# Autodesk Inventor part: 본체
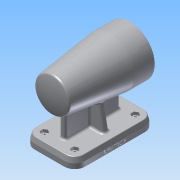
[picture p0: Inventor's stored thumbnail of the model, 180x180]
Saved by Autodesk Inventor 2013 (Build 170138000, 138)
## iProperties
Created: 2017-01
Part Number: 본체
Material: 알루미늄 6061
Document SubType Name: Modeling
Designer: Administrator
Density: 2.71 g/cm^3
Mass: 795.659 g
Surface Area: 660.761 cm^2
Volume: 293.601 cm^3
Author: Administrator
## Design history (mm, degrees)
sketch "스케치3"
  geometry: L1 (56, 35)-(-56, 35); L2 (-56, 35)-(-56, -35); L3 (-56, -35)-(56, -35); L4 (56, -35)-(56, 35); L5 (56, 35)-(-56, -35); L6 (-56, 35)-(56, -35); 3 further points
  constraints: 12 end point, 3 midpoint, 2 parallel, 1 coincident, 1 horizontal, 1 perpendicular
  dimensions: "d0" = 112 distance of L2.end L3.end; "d2" = 70 distance of L1.end L2.end
extrude "돌출1" new body sketch "스케치3" distance "d3" = 14; taper "d4" = 0 deg
sketch "스케치4"
  geometry: L1 (56, 0)-(-56, 0) reference; L2 (56, 74)-(-56, 74); L3 (56, 74)-(56, 108); L4 (56, 108)-(28, 108); L5 (28, 108)-(-52.27, 98.144); A1 r 80 centre (24, 74) between (-52.27, 98.144) and (-56, 74); 3 further points
  constraints: 8 end point, 2 midpoint, 2 perpendicular, 2 point on circle, 1 centre point, 1 parallel, 1 point on line, 1 vertical alignment
  dimensions: "d5" = 74 distance from line of L2 point (0, 0); "d7" = 112 distance of L2.end L2.start; "d8" = 7 deg angle of L4 L5; "d9" = 28 distance of L3.end L4.end; "d10" = 68 diameter of L4 L2; "d12" = 160 diameter of A1
revolve "회전1" sketch "스케치4" stored, may be unused: angle "d14" = 90 deg
sketch "스케치5"
  geometry: L1 (56, 40)-(56, 108) reference; L2 (56, 74)-(-56, 74); L3 (56, 74)-(56, 95); L4 (56, 95)-(41, 95); L5 (41, 95)-(41, 98); L6 (41, 98)-(-13, 98); L7 (-13, 98)-(-13, 95); L8 (-13, 95)-(-25, 95); L9 (-25, 95)-(-25, 91.5); L10 (-25, 91.5)-(-43, 91.5); L11 (-43, 91.5)-(-43, 90); L12 (-43, 90)-(-47, 90); L13 (-47, 90)-(-47, 84.5); L14 (-47, 84.5)-(-50, 84.5); L15 (-50, 84.5)-(-50, 74); 2 further points
  constraints: 28 end point, 8 perpendicular, 3 parallel, 2 midpoint, 2 point on line, 1 collinear, 1 vertical
  dimensions: "d15" = 112 distance of L2.start L2.end; "d17" = 42 diameter of L4 L2; "d18" = 48 diameter of L6 L2; "d19" = 42 diameter of L8 L2; "d20" = 35 diameter of L10 L2; "d21" = 32 diameter of L12 L2; "d22" = 21 diameter of L14 L2; "d23" = 3 distance of L13.end L14.end; "d24" = 15 distance of L3.end L4.end; "d25" = 54 distance of L5.end L6.end; "d26" = 18 distance of L9.end L10.end; "d28" = 4 distance of L11.end L12.end; "d29" = 12 distance of L7.end L8.end
revolve "회전2" sketch "스케치5" stored, may be unused: angle "d30" = 90 deg
sketch "스케치6"
  geometry: L1 (-38, -4)-(38, -4); L2 (38, -4)-(38, 4); L3 (38, 4)-(-38, 4); L4 (-38, 4)-(-38, -4); L5 (-38, -4)-(38, 4); L6 (38, -4)-(-38, 4); L7 (-56, 35)-(-56, -35) reference; 3 further points
  constraints: 12 end point, 3 midpoint, 2 parallel, 1 coincident, 1 horizontal, 1 perpendicular
  dimensions: "d31" = 18 distance between parallel lines of L4 L7; "d32" = 8 distance of L3.end L1.start
extrude "돌출2" join sketch "스케치6" stored distance "d33" = 14; taper "d34" = 0 deg
sketch "스케치7"
  geometry: L1 (14, -35)-(14, 35) reference; L2 (49.169, 16.799)-(14, 23); L3 (14, 23)-(14, -23); L4 (14, -23)-(49.169, -16.799); L5 (0, 35)-(14, 35) reference; L6 (0, -35)-(14, -35) reference; L7 (49.169, 16.799)-(49.169, -16.799); 2 further points
  constraints: 8 end point, 1 collinear, 1 horizontal alignment, 1 midpoint, 1 perpendicular, 1 vertical
  dimensions: "d35" = 12 distance from line of L2.end L5; "d36" = 12 distance from line of L6 L3.end; "d37" = 100 deg angle of L2 L1; "d38" = 100 deg angle of L1 L4
extrude "돌출3" join sketch "스케치7" stored distance "d39" = 8; taper "d40" = 0 deg
fillet "모깎기1" dims "d41" = 14.5
sketch "스케치8"
  geometry: L1 (41.5, 35)-(-41.5, 35) reference; L2 (-56, 20.5)-(-56, -20.5) reference; L3 (-41.5, -35)-(41.5, -35) reference; L4 (56, -20.5)-(56, 20.5) reference; A1 r 14.5 centre (-41.5, 20.5) between (-41.5, 35) and (-56, 20.5) reference; A2 r 14.5 centre (-41.5, -20.5) between (-56, -20.5) and (-41.5, -35) reference; A3 r 14.5 centre (41.5, -20.5) between (41.5, -35) and (56, -20.5) reference; A4 r 14.5 centre (41.5, 20.5) between (56, 20.5) and (41.5, 35) reference; 1 further point
extrude "돌출4" cut sketch "스케치8" distance "d42" = 7; taper "d43" = 0 deg
sketch "스케치9"
  geometry: L1 (56, -20.5)-(56, 20.5) reference; L2 (-41.5, -35)-(41.5, -35) reference; L3 (-56, 20.5)-(-56, -20.5) reference; L4 (41.5, 35)-(-41.5, 35) reference; A1 r 14.5 centre (41.5, 20.5) between (56, 20.5) and (41.5, 35) reference; A2 r 14.5 centre (41.5, -20.5) between (41.5, -35) and (56, -20.5) reference; A3 r 14.5 centre (-41.5, -20.5) between (-56, -20.5) and (-41.5, -35) reference; A4 r 14.5 centre (-41.5, 20.5) between (-41.5, 35) and (-56, 20.5) reference; 1 further point
extrude "돌출5" join sketch "스케치9" distance "d44" = 7; taper "d45" = -15 deg
fillet "모깎기2" dims "d46" = 1
fillet "모깎기3" dims "d47" = 0.3
fillet "모깎기4" dims "d48" = 3
fillet "모깎기5" dims "d49" = 3
chamfer "모따기1" distance "d50" = 1; stored, may be unused: second distance "d51" = 2, angle "d52" = 45 deg
fillet "모깎기6" dims "d53" = 3
fillet "모깎기7" dims "d54" = 3
fillet "모깎기8" dims "d55" = 3
sketch "스케치10"
  geometry: C1 r 34 at (0, 0) reference; 2 further points
  constraints: 1 vertical alignment
  dimensions: "d56" = 26 distance of point (0, 26) C1.centre
hole "구멍1" sketch "스케치10" at (0, 26) diameter "d57" = 3.242; stored, may be unused: countersink angle "d61" = 90 deg, drill point angle "d63" = 118 deg; dims "d58" = 8, "d59" = 4, "d60" = 2, "d62" = 11
sketch "스케치11" dims "d72" = 10
  geometry: L1 (-41.5, 35)-(41.5, 35) reference; L2 (-56, -20.5)-(-56, 20.5) reference; L3 (-37, 21)-(-39.5, 16.67); L4 (-39.5, 16.67)-(-44.5, 16.67); L5 (-44.5, 16.67)-(-47, 21); L6 (-47, 21)-(-44.5, 25.33); L7 (-44.5, 25.33)-(-39.5, 25.33); L8 (-39.5, 25.33)-(-37, 21); 4 further points
  constraints: 12 end point, 2 coincident, 1 horizontal alignment, 15 other
  dimensions: "d70" = 14 distance from line of point (-42, 21) L1; "d71" = 14 distance from line of point (-42, 21) L2; "d73" = 4.33013 vertical distance of L7.end L3.start
extrude "돌출6" cut sketch "스케치11" distance "d77" = 4; taper "d78" = 0 deg
sketch "스케치12"
  geometry: L1 (-44.5, -25.33)-(-39.5, -25.33) reference; L2 (-39.5, -25.33)-(-37, -21) reference; L3 (-37, -21)-(-39.5, -16.67) reference; L4 (-39.5, -16.67)-(-44.5, -16.67) reference; L5 (-44.5, -16.67)-(-47, -21) reference; L6 (-47, -21)-(-44.5, -25.33) reference; L7 (-47, -21)-(-37, -21); L8 (-39.5, -25.33)-(-44.5, -16.67); L9 (-44.5, -25.33)-(-39.5, -16.67); 2 further points
  constraints: 6 end point, 2 parallel, 1 midpoint
hole "구멍2" sketch "스케치12" at (-42, -21) diameter "d79" = 5; stored, may be unused: countersink angle "d83" = 90 deg, drill point angle "d85" = 118 deg; dims "d80" = 8, "d81" = 4, "d82" = 2, "d84" = 15
sketch "스케치13"
  geometry: L1 (97.5, 0)-(97.5, 7) reference; 2 further points
  constraints: 1 other
  dimensions: "d89" = 4 distance of point (41.5, 0) point (41.5, 4); "d90" = 56 distance from line of L1 point (41.5, 4)
feature "엠보싱1" sketch "스케치13" dims "d0" = 112, "d2" = 70, "d91" = 0.5, "d92" = 0
fillet "모깎기9" dims "d93" = 3
node "솔리드1"
pattern_circular "원형 패턴1" dims angle "d65" = 360 deg
pattern_linear "직사각형 패턴1" dims "d88" = 42
mirror "대칭1"
mirror "대칭2"
node "투영된 루프1"
